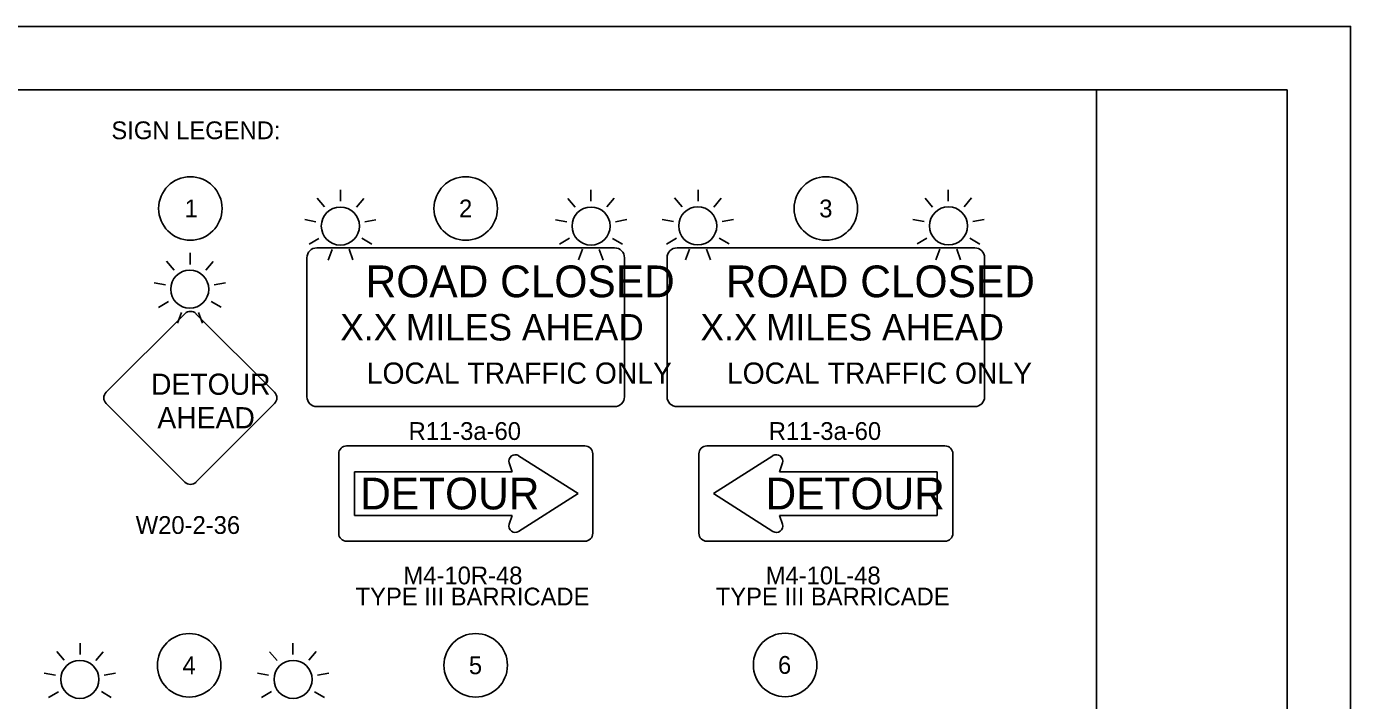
# Model space of a CAD drawing. Extents: x 0 to 680, y 0 to 440.
# Drawn here: x 471.5 to 680, y 333.9 to 440 of the extents above; entities that cross this region are included whole.
import ezdxf

# ---------------------------------------------------------------- set-up
doc = ezdxf.new("R2010")
doc.units = 0
for name, color, linetype in [('AP_X_Lights', 7, 'Continuous'), ('SH_Border', 7, 'Continuous'), ('SH_Cut_Line', 7, 'Continuous'), ('SH_Text', 7, 'Continuous'), ('SN_P_Signs', 7, 'Continuous'), ('SN_P_Text', 7, 'Continuous')]:
    doc.layers.add(name, color=color, linetype=linetype)

msp = doc.modelspace()

# ---------------------------------------------------------------- linework, layer by layer
at = {"layer": 'AP_X_Lights'}
for p, q in [((518.46, 411.58), (517.3, 412.96)), ((520.98, 412.47), (520.98, 414.27)), ((523.47, 411.54), (524.62, 412.92)), ((557.89, 411.54), (556.74, 412.92)), ((560.38, 412.47), (560.38, 414.27)), ((562.9, 411.58), (564.06, 412.96)), ((574.74, 411.61), (573.58, 412.99)), ((577.26, 412.5), (577.26, 414.3)), ((579.75, 411.57), (580.9, 412.95)), ((614.17, 411.57), (613.01, 412.95)), ((616.66, 412.5), (616.66, 414.3)), ((619.18, 411.61), (620.33, 412.99)), ((517.1, 409.26), (515.33, 409.58)), ((524.78, 409.25), (526.55, 409.56)), ((556.58, 409.25), (554.81, 409.56)), ((564.26, 409.26), (566.03, 409.58)), ((573.38, 409.29), (571.61, 409.6)), ((581.06, 409.28), (582.83, 409.59)), ((612.86, 409.28), (611.08, 409.59)), ((620.54, 409.29), (622.31, 409.6)), ((517.57, 406.61), (516.01, 405.71)), ((524.33, 406.64), (525.89, 405.74)), ((557.03, 406.64), (555.47, 405.74)), ((563.79, 406.61), (565.35, 405.71)), ((573.85, 406.64), (572.29, 405.74)), ((580.61, 406.67), (582.17, 405.77)), ((613.31, 406.67), (611.75, 405.77)), ((620.07, 406.64), (621.63, 405.74)), ((519.64, 404.89), (519.02, 403.2)), ((522.31, 404.92), (522.93, 403.23)), ((559.05, 404.92), (558.43, 403.23)), ((561.72, 404.89), (562.34, 403.2)), ((575.92, 404.92), (575.3, 403.23)), ((578.59, 404.95), (579.21, 403.26)), ((615.33, 404.95), (614.71, 403.26)), ((618, 404.92), (618.61, 403.23)), ((494.75, 401.64), (493.59, 403.02)), ((497.27, 402.53), (497.27, 404.33)), ((499.75, 401.6), (500.91, 402.98)), ((493.39, 399.32), (491.62, 399.63)), ((501.07, 399.31), (502.84, 399.62)), ((493.86, 396.67), (492.3, 395.77)), ((500.62, 396.7), (502.18, 395.8)), ((495.93, 394.95), (495.31, 393.26)), ((498.6, 394.98), (499.21, 393.29)), ((479.96, 341.08), (479.96, 342.88)), ((513.45, 341.08), (513.45, 342.88)), ((477.44, 340.19), (476.29, 341.57)), ((482.45, 340.15), (483.61, 341.53)), ((510.97, 340.15), (509.81, 341.53)), ((515.97, 340.19), (517.13, 341.57)), ((476.09, 337.87), (474.31, 338.18)), ((483.76, 337.86), (485.54, 338.17)), ((509.65, 337.86), (507.88, 338.17)), ((517.33, 337.87), (519.11, 338.18)), ((476.55, 335.22), (474.99, 334.32)), ((483.31, 335.25), (484.87, 334.35)), ((510.1, 335.25), (508.55, 334.35)), ((516.87, 335.22), (518.42, 334.32))]:
    msp.add_line(p, q, dxfattribs=at)
for centre in [(520.94, 408.57), (560.42, 408.57), (577.22, 408.6), (616.7, 408.6), (497.23, 398.63), (479.92, 337.18), (513.5, 337.18)]:
    msp.add_circle(centre, 3, dxfattribs=at)
at = {"layer": 'SH_Border'}
msp.add_line((640, 10), (640, 430), dxfattribs=at)
msp.add_lwpolyline([(30, 430), (670, 430), (670, 10), (30, 10)], close=True, dxfattribs=at)
at = {"layer": 'SH_Cut_Line'}
msp.add_lwpolyline([(0, 0), (680, 0), (680, 440), (0, 440)], close=True, dxfattribs=at)
at = {"layer": 'SN_P_Signs'}
for p, q in [((547.53, 371.26), (547.97, 369.88)), ((558.39, 366.44), (549.01, 372.41)), ((579.68, 366.44), (589.05, 372.41)), ((590.54, 371.26), (590.09, 369.88)), ((547.97, 369.88), (523.18, 369.88)), ((523.18, 369.88), (523.18, 363)), ((590.09, 369.88), (614.89, 369.88)), ((614.89, 369.88), (614.89, 363)), ((549.01, 360.47), (558.39, 366.44)), ((589.05, 360.47), (579.68, 366.44)), ((523.18, 363), (547.97, 363)), ((547.97, 363), (547.53, 361.61)), ((614.89, 363), (590.09, 363)), ((590.09, 363), (590.54, 361.61))]:
    msp.add_line(p, q, dxfattribs=at)
for points in [[(564.12, 405.14), (517.24, 405.14)], [(620.82, 405.14), (573.95, 405.14)], [(515.68, 403.58), (515.68, 381.7)], [(565.68, 381.7), (565.68, 403.58)], [(572.39, 403.58), (572.39, 381.7)], [(622.39, 381.7), (622.39, 403.58)], [(484.07, 382.4), (496.44, 394.77)], [(498.21, 394.77), (510.58, 382.4)], [(496.44, 368.26), (484.07, 380.63)], [(510.58, 380.63), (498.21, 368.26)], [(517.24, 380.14), (564.12, 380.14)], [(573.95, 380.14), (620.82, 380.14)], [(521.93, 373.94), (559.43, 373.94)], [(616.14, 373.94), (578.64, 373.94)], [(520.68, 360.19), (520.68, 372.69)], [(560.68, 372.69), (560.68, 360.19)], [(577.39, 372.69), (577.39, 360.19)], [(617.39, 360.19), (617.39, 372.69)], [(559.43, 358.94), (521.93, 358.94)], [(578.64, 358.94), (616.14, 358.94)]]:
    msp.add_lwpolyline(points, dxfattribs=at)
for centre in [(497.33, 411.34), (540.68, 411.34), (597.39, 411.34), (497.14, 339.4), (542.25, 339.4), (590.97, 339.46)]:
    msp.add_circle(centre, 5, dxfattribs=at)
for centre, radius, start, end in [((517.24, 403.58), 1.56, 90, 180), ((564.12, 403.58), 1.56, 0, 90), ((573.95, 403.58), 1.56, 90, 180), ((620.82, 403.58), 1.56, 0, 90), ((497.33, 393.89), 1.25, 45, 135), ((484.95, 381.51), 1.25, 135, 225), ((509.7, 381.51), 1.25, 315, 45), ((517.24, 381.7), 1.56, 180, 270), ((564.12, 381.7), 1.56, 270, 0), ((573.95, 381.7), 1.56, 180, 270), ((620.82, 381.7), 1.56, 270, 0), ((521.93, 372.69), 1.25, 90, 180), ((559.43, 372.69), 1.25, 0, 90), ((578.64, 372.69), 1.25, 90, 180), ((616.14, 372.69), 1.25, 0, 90), ((548.48, 371.57), 1, 57.4891, 197.8189), ((589.59, 371.57), 1, 342.1811, 122.5109), ((497.33, 369.14), 1.25, 225, 315), ((548.48, 361.31), 1, 162.1811, 302.5109), ((589.59, 361.31), 1, 237.4891, 17.8189), ((521.93, 360.19), 1.25, 180, 270), ((559.43, 360.19), 1.25, 270, 360), ((578.64, 360.19), 1.25, 180, 270), ((616.14, 360.19), 1.25, 270, 0)]:
    msp.add_arc(centre, radius, start, end, dxfattribs=at)

# ---------------------------------------------------------------- texts
at = {"layer": 'SH_Text'}
for s, p in [('SIGN LEGEND:', (484.89, 422.25)), ('TYPE III BARRICADE', (523.34, 348.83)), ('TYPE III BARRICADE', (580.05, 348.83))]:
    msp.add_text(s, height=2.8, dxfattribs=at).set_placement(p)
at = {"layer": 'SN_P_Signs'}
for s, height, p in [('1', 2.8, (496.41, 409.94)), ('2', 2.8, (539.63, 409.94)), ('3', 2.8, (596.35, 409.94)), ('ROAD CLOSED', 5, (524.92, 397.36)), ('ROAD CLOSED', 5, (581.63, 397.36)), ('X.X', 4.167, (520.92, 390.55)), ('MILES AHEAD', 4.1667, (531.26, 390.55)), ('X.X', 4.167, (577.63, 390.55)), ('MILES AHEAD', 4.1667, (587.96, 390.55)), ('LOCAL TRAFFIC ONLY', 3.3333, (525.1, 383.75)), ('LOCAL TRAFFIC ONLY', 3.3333, (581.81, 383.75)), ('DETOUR', 3.333, (491.13, 382)), ('AHEAD', 3.333, (492.13, 376.72)), ('DETOUR', 5, (524.06, 363.95)), ('DETOUR', 5, (587.89, 363.95)), ('4', 2.8, (496.1, 338)), ('5', 2.8, (541.18, 338)), ('6', 2.8, (589.85, 338.06))]:
    msp.add_text(s, height=height, dxfattribs=at).set_placement(p)
at = {"layer": 'SN_P_Text'}
for s, p in [('R11-3a-60', (531.69, 374.89)), ('R11-3a-60', (588.4, 374.89)), ('W20-2-36', (488.72, 360.09)), ('M4-10R-48', (530.88, 352.15)), ('M4-10L-48', (587.91, 352.15))]:
    msp.add_text(s, height=2.8, dxfattribs=at).set_placement(p)

doc.saveas('drawing.dxf')
